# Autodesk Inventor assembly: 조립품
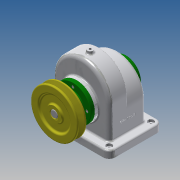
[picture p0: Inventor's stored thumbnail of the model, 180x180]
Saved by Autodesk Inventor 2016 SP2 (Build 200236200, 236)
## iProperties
Created: 2017-11
Part Number: 조립품
Document SubType Name: Assembly
Designer: Administrator
Author: Administrator
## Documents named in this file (14)
- D:\최정현\471107V1006\OldVersions\조립품.iam
- D:\최정현\471107V1006\본체.ipt
- D:\최정현\471107V1006\축.ipt
- D:\최정현\471107V1006\키 - 6 x 6 x 22.ipt
- D:\최정현\471107V1006\베어링 6002.ipt
- D:\최정현\471107V1006\키 - 5 x 5 x 18.ipt
- D:\최정현\471107V1006\V-벨트풀리.ipt
- D:\최정현\471107V1006\멈춤나사 - M4 x 10.ipt
- 멈춤나사 - M4 x 10.ipt
- D:\최정현\471107V1006\스퍼기어.ipt
- D:\최정현\471107V1006\오일 실 15 30 7.ipt
- D:\최정현\471107V1006\앞커버.ipt
- D:\최정현\471107V1006\볼트 M3 x 8.ipt
- D:\최정현\471107V1006\뒤커버.ipt
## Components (1 placed, 1 different names)
1. V-벨트풀리:1
